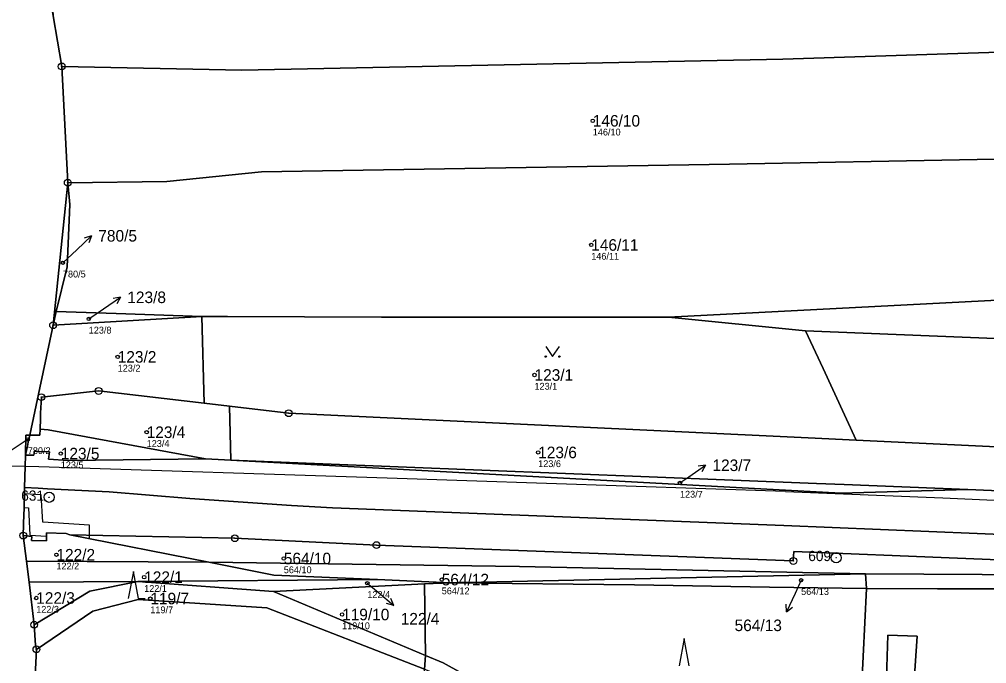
# Model space of a CAD drawing. Extents: x -732749 to -730903, y -1025757 to -1023435.
# Drawn here: x -732610 to -732467.8, y -1024807.5 to -1024712.7 of the extents above; entities that cross this region are included whole.
import ezdxf

# ---------------------------------------------------------------- set-up
doc = ezdxf.new("R2010")
doc.units = 0
for name, color, linetype in [('Definiční body', 7, 'Continuous'), ('Hranice parcel', 7, 'Continuous'), ('Parcelní čísla', 7, 'Continuous'), ('Polygon budovy', 7, 'Continuous'), ('Polygon parcely', 7, 'Continuous'), ('Pop  PČ popisy', 7, 'Continuous'), ('Poz předměty', 7, 'Continuous'), ('Věcná břemena k části', 7, 'Continuous'), ('Značky bodu BP', 7, 'Continuous'), ('Značky kultur', 7, 'Continuous')]:
    doc.layers.add(name, color=color, linetype=linetype)

msp = doc.modelspace()

# ---------------------------------------------------------------- linework, layer by layer
at = {"layer": 'Definiční body'}
for centre in [(-732525.66, -1024727.65), (-732525.89, -1024745.91), (-732603.56, -1024748.53), (-732599.77, -1024756.78), (-732595.51, -1024762.37), (-732534.23, -1024765.03), (-732591.25, -1024773.45), (-732608.73, -1024774.5), (-732603.88, -1024776.59), (-732533.69, -1024776.42), (-732512.84, -1024780.91), (-732604.52, -1024791.47), (-732571.09, -1024792.02), (-732591.62, -1024794.77), (-732547.87, -1024795.12), (-732495.03, -1024795.22), (-732558.81, -1024795.66), (-732607.49, -1024797.83), (-732590.71, -1024797.91), (-732562.52, -1024800.26)]:
    msp.add_circle(centre, 0.25, dxfattribs=at)
at = {"layer": 'Hranice parcel'}
for p, q in [((-732603.74, -1024719.65), (-732604.99, -1024712.19)), ((-732602.85, -1024736.75), (-732603.74, -1024719.65)), ((-732602.85, -1024736.75), (-732605.01, -1024757.71)), ((-732514.51, -1024756.52), (-732430.15, -1024752.17)), ((-732605.01, -1024757.71), (-732604.58, -1024755.68)), ((-732583.12, -1024756.45), (-732605.01, -1024757.71)), ((-732583.12, -1024756.45), (-732582.8, -1024769.2)), ((-732494.37, -1024758.56), (-732514.51, -1024756.52)), ((-732582.8, -1024769.2), (-732579.08, -1024769.64)), ((-732578.9, -1024777.57), (-732579.08, -1024769.64)), ((-732582.6, -1024777.37), (-732578.9, -1024777.57)), ((-732608.93, -1024792.4), (-732609.39, -1024788.65)), ((-732602.56, -1024788.52), (-732582.1, -1024792.58)), ((-732582.1, -1024792.58), (-732608.93, -1024792.4)), ((-732608.93, -1024792.4), (-732608.55, -1024795.52)), ((-732592.56, -1024795.4), (-732557.32, -1024795.12)), ((-732546.51, -1024795.58), (-732557.32, -1024795.12)), ((-732546.51, -1024795.58), (-732485.56, -1024794.26)), ((-732485.43, -1024796.42), (-732485.56, -1024794.26)), ((-732485.56, -1024794.26), (-732442.64, -1024794.52)), ((-732608.55, -1024795.52), (-732592.56, -1024795.4)), ((-732607.79, -1024801.77), (-732608.55, -1024795.52)), ((-732592.56, -1024795.4), (-732599.62, -1024796.8)), ((-732572.58, -1024796.88), (-732592.56, -1024795.4)), ((-732550.41, -1024795.77), (-732572.58, -1024796.88)), ((-732546.51, -1024795.58), (-732550.41, -1024795.77)), ((-732550.41, -1024795.77), (-732550.27, -1024806.28)), ((-732599.62, -1024796.8), (-732607.79, -1024801.77)), ((-732550.27, -1024806.28), (-732572.58, -1024796.88)), ((-732607.79, -1024801.77), (-732607.6, -1024804.78)), ((-732607.6, -1024804.78), (-732607.46, -1024805.38)), ((-732550.4, -1024808.31), (-732550.27, -1024806.28))]:
    msp.add_line(p, q, dxfattribs=at)
for points in [[(-732603.74, -1024719.65), (-732577.26, -1024720.21), (-732497.7, -1024718.61), (-732435.68, -1024716.6)], [(-732602.85, -1024736.75), (-732588.3, -1024736.57), (-732574.35, -1024735.17), (-732505.57, -1024734.04), (-732432.75, -1024732.67)], [(-732604.58, -1024755.68), (-732602.94, -1024749.11), (-732602.54, -1024739.97), (-732602.85, -1024736.75)], [(-732583.12, -1024756.45), (-732595.74, -1024756), (-732604.58, -1024755.68)], [(-732514.51, -1024756.52), (-732556.73, -1024756.51), (-732579.37, -1024756.45), (-732583.12, -1024756.45)], [(-732605.01, -1024757.71), (-732606.97, -1024766.94), (-732608.44, -1024773.87)], [(-732486.92, -1024774.63), (-732491.8, -1024764.09), (-732494.37, -1024758.56)], [(-732429.16, -1024761.7), (-732451.94, -1024760.24), (-732494.37, -1024758.56)], [(-732606.93, -1024773), (-732606.87, -1024771.48), (-732606.87, -1024770.65), (-732606.73, -1024768.29), (-732598.31, -1024767.38), (-732582.8, -1024769.2)], [(-732579.08, -1024769.64), (-732570.37, -1024770.66), (-732494.01, -1024774.29), (-732486.92, -1024774.63)], [(-732608.44, -1024773.87), (-732609.01, -1024773.86), (-732609.06, -1024776.81)], [(-732608.44, -1024773.87), (-732608.66, -1024774.93), (-732608.78, -1024775.48), (-732608.92, -1024776.13), (-732609.06, -1024776.81)], [(-732608.44, -1024773.87), (-732606.95, -1024773.88), (-732606.93, -1024773)], [(-732606.93, -1024773), (-732605.75, -1024773.12), (-732582.6, -1024777.37)], [(-732486.92, -1024774.63), (-732460.13, -1024775.9), (-732426.87, -1024778.43)], [(-732609.06, -1024776.81), (-732609.11, -1024778.5), (-732609.19, -1024781.6)], [(-732609.06, -1024776.81), (-732607.83, -1024776.81), (-732607.73, -1024776.23), (-732607.04, -1024776.26), (-732605.52, -1024776.32), (-732605.67, -1024777.42), (-732602.77, -1024777.63), (-732582.6, -1024777.37)], [(-732578.9, -1024777.57), (-732492.78, -1024780.98), (-732488.72, -1024781.14), (-732470.51, -1024781.88)], [(-732578.9, -1024777.57), (-732489.2, -1024782.39), (-732470.51, -1024781.88)], [(-732609.19, -1024781.6), (-732609.21, -1024782.24), (-732609.22, -1024782.52), (-732609.27, -1024784.52), (-732609.28, -1024784.79), (-732609.3, -1024785.43), (-732609.39, -1024788.65)], [(-732369.58, -1024795.34), (-732369.92, -1024794.44), (-732372.64, -1024792.79), (-732375.72, -1024792.25), (-732378.8, -1024792.04), (-732447.85, -1024789.23), (-732497.58, -1024787.17), (-732563.92, -1024784.56), (-732569.94, -1024784.24), (-732584.9, -1024783.22), (-732596.78, -1024782.21), (-732605.81, -1024781.79), (-732607.18, -1024781.66), (-732609.19, -1024781.6)], [(-732470.51, -1024781.88), (-732455.49, -1024782.49), (-732426.01, -1024783.68)], [(-732609.39, -1024788.65), (-732608.14, -1024788.8), (-732608.17, -1024789.39), (-732605.97, -1024789.44), (-732605.97, -1024788.27), (-732603.07, -1024788.35), (-732602.56, -1024788.52)], [(-732602.56, -1024788.52), (-732578.29, -1024789.04), (-732557.47, -1024790.05), (-732496.18, -1024792.38), (-732496.12, -1024790.97), (-732448, -1024792.93), (-732420.02, -1024794.07)], [(-732582.1, -1024792.58), (-732536.43, -1024793.21), (-732485.56, -1024794.26)], [(-732557.32, -1024795.12), (-732572.56, -1024794.47), (-732582.1, -1024792.58)], [(-732485.43, -1024796.42), (-732499.66, -1024796.22), (-732519.54, -1024795.9), (-732546.51, -1024795.58)], [(-732486.86, -1024825.68), (-732486.41, -1024816.41), (-732485.43, -1024796.42)], [(-732442.57, -1024796.49), (-732474.99, -1024796.48), (-732485.43, -1024796.42)], [(-732550.4, -1024808.31), (-732573.59, -1024799.29), (-732592.51, -1024798.07), (-732599.17, -1024799.75), (-732607.46, -1024805.38)], [(-732478.6, -1024812.92), (-732477.97, -1024803.45), (-732482.27, -1024803.31), (-732482.56, -1024812.7), (-732483.01, -1024812.67), (-732482.98, -1024816.43), (-732486.41, -1024816.41), (-732486.51, -1024822.83), (-732480.44, -1024822.93), (-732470.38, -1024823.14), (-732470.24, -1024816.4), (-732470.26, -1024814.3), (-732472.8, -1024814.19), (-732478.6, -1024814.1), (-732478.6, -1024812.92)], [(-732607.46, -1024805.38), (-732607.76, -1024811.21), (-732610.88, -1024850.88)], [(-732550.27, -1024806.28), (-732547.68, -1024807.37), (-732535.68, -1024813.99), (-732518.46, -1024823.83), (-732512.12, -1024826.36), (-732506.19, -1024827.78), (-732486.98, -1024830.41)]]:
    msp.add_lwpolyline(points, dxfattribs=at)
at = {"layer": 'Polygon budovy'}
msp.add_lwpolyline([(-732482.57, -1024812.99), (-732481.51, -1024812.81), (-732481.6, -1024816.44), (-732480.33, -1024816.52), (-732480.44, -1024822.93), (-732470.38, -1024823.14), (-732470.24, -1024816.4), (-732472.85, -1024816.34), (-732472.8, -1024814.19), (-732478.6, -1024814.1), (-732478.6, -1024812.92), (-732477.97, -1024803.45), (-732482.27, -1024803.31), (-732482.56, -1024812.7)], close=True, dxfattribs=at)
at = {"layer": 'Polygon parcely'}
for points in [[(-732607.76, -1024811.21), (-732607.46, -1024805.38), (-732607.6, -1024804.78), (-732607.79, -1024801.77), (-732608.55, -1024795.52), (-732608.93, -1024792.4), (-732609.39, -1024788.65), (-732609.3, -1024785.43), (-732609.28, -1024784.79), (-732609.27, -1024784.52), (-732609.22, -1024782.52), (-732609.21, -1024782.24), (-732609.19, -1024781.6), (-732609.11, -1024778.5), (-732609.06, -1024776.81), (-732609.01, -1024773.86), (-732608.44, -1024773.87), (-732606.97, -1024766.94), (-732605.01, -1024757.71), (-732602.85, -1024736.75), (-732603.74, -1024719.65), (-732604.99, -1024712.19), (-732607.31, -1024698.36), (-732611.24, -1024594.48)], [(-732455.49, -1024782.49), (-732470.51, -1024781.88), (-732489.2, -1024782.39), (-732578.9, -1024777.57), (-732582.6, -1024777.37), (-732602.77, -1024777.63), (-732605.67, -1024777.42), (-732605.52, -1024776.32), (-732607.04, -1024776.26), (-732607.73, -1024776.23), (-732607.83, -1024776.81), (-732609.06, -1024776.81), (-732609.11, -1024778.5), (-732609.19, -1024781.6), (-732607.18, -1024781.66), (-732605.81, -1024781.79), (-732596.78, -1024782.21), (-732584.9, -1024783.22), (-732569.94, -1024784.24), (-732563.92, -1024784.56), (-732497.58, -1024787.17), (-732447.85, -1024789.23)], [(-732447.85, -1024789.23), (-732497.58, -1024787.17), (-732563.92, -1024784.56), (-732569.94, -1024784.24), (-732584.9, -1024783.22), (-732596.78, -1024782.21), (-732605.81, -1024781.79), (-732607.18, -1024781.66), (-732609.19, -1024781.6), (-732609.21, -1024782.24), (-732609.22, -1024782.52), (-732609.27, -1024784.52), (-732609.28, -1024784.79), (-732609.3, -1024785.43), (-732609.39, -1024788.65), (-732608.14, -1024788.8), (-732608.17, -1024789.39), (-732605.97, -1024789.44), (-732605.97, -1024788.27), (-732603.07, -1024788.35), (-732602.56, -1024788.52), (-732578.29, -1024789.04), (-732557.47, -1024790.05), (-732496.18, -1024792.38), (-732496.12, -1024790.97), (-732448, -1024792.93)]]:
    msp.add_lwpolyline(points, dxfattribs=at)
for points in [[(-732577.26, -1024720.21), (-732497.7, -1024718.61), (-732435.68, -1024716.6), (-732438.93, -1024698.81), (-732441.15, -1024698.99), (-732470.31, -1024699.59), (-732479, -1024699.78), (-732497.59, -1024700.32), (-732497.8, -1024697.68), (-732523.82, -1024698.02), (-732605.8, -1024698.35), (-732605.62, -1024703.18), (-732604.99, -1024712.19), (-732603.74, -1024719.65)], [(-732432.75, -1024732.67), (-732435.68, -1024716.6), (-732497.7, -1024718.61), (-732577.26, -1024720.21), (-732603.74, -1024719.65), (-732602.85, -1024736.75), (-732588.3, -1024736.57), (-732574.35, -1024735.17), (-732505.57, -1024734.04)], [(-732514.51, -1024756.52), (-732430.15, -1024752.17), (-732431.44, -1024739.85), (-732432.75, -1024732.67), (-732505.57, -1024734.04), (-732574.35, -1024735.17), (-732588.3, -1024736.57), (-732602.85, -1024736.75), (-732602.54, -1024739.97), (-732602.94, -1024749.11), (-732604.58, -1024755.68), (-732595.74, -1024756), (-732583.12, -1024756.45), (-732579.37, -1024756.45), (-732556.73, -1024756.51)], [(-732605.01, -1024757.71), (-732604.58, -1024755.68), (-732602.94, -1024749.11), (-732602.54, -1024739.97), (-732602.85, -1024736.75)], [(-732514.51, -1024756.52), (-732494.37, -1024758.56), (-732451.94, -1024760.24), (-732429.16, -1024761.7), (-732430.15, -1024752.17)], [(-732606.97, -1024766.94), (-732608.44, -1024773.87), (-732606.95, -1024773.88), (-732606.93, -1024773), (-732606.87, -1024771.48), (-732606.87, -1024770.65), (-732606.73, -1024768.29), (-732598.31, -1024767.38), (-732582.8, -1024769.2), (-732583.12, -1024756.45), (-732605.01, -1024757.71)], [(-732595.74, -1024756), (-732604.58, -1024755.68), (-732605.01, -1024757.71), (-732583.12, -1024756.45)], [(-732486.92, -1024774.63), (-732491.8, -1024764.09), (-732494.37, -1024758.56), (-732514.51, -1024756.52), (-732556.73, -1024756.51), (-732579.37, -1024756.45), (-732583.12, -1024756.45), (-732582.8, -1024769.2), (-732579.08, -1024769.64), (-732570.37, -1024770.66), (-732494.01, -1024774.29)], [(-732429.16, -1024761.7), (-732451.94, -1024760.24), (-732494.37, -1024758.56), (-732491.8, -1024764.09), (-732486.92, -1024774.63), (-732460.13, -1024775.9), (-732426.87, -1024778.43), (-732427.58, -1024773.67), (-732428.01, -1024770.76)], [(-732605.75, -1024773.12), (-732582.6, -1024777.37), (-732578.9, -1024777.57), (-732579.08, -1024769.64), (-732582.8, -1024769.2), (-732598.31, -1024767.38), (-732606.73, -1024768.29), (-732606.87, -1024770.65), (-732606.87, -1024771.48), (-732606.93, -1024773)], [(-732470.51, -1024781.88), (-732455.49, -1024782.49), (-732426.01, -1024783.68), (-732426.87, -1024778.43), (-732460.13, -1024775.9), (-732486.92, -1024774.63), (-732494.01, -1024774.29), (-732570.37, -1024770.66), (-732579.08, -1024769.64), (-732578.9, -1024777.57), (-732492.78, -1024780.98), (-732488.72, -1024781.14)], [(-732605.52, -1024776.32), (-732605.67, -1024777.42), (-732602.77, -1024777.63), (-732582.6, -1024777.37), (-732605.75, -1024773.12), (-732606.93, -1024773), (-732606.95, -1024773.88), (-732608.44, -1024773.87), (-732608.66, -1024774.93), (-732608.78, -1024775.48), (-732608.92, -1024776.13), (-732609.06, -1024776.81), (-732607.83, -1024776.81), (-732607.73, -1024776.23), (-732607.04, -1024776.26)], [(-732608.44, -1024773.87), (-732609.01, -1024773.86), (-732609.06, -1024776.81), (-732608.92, -1024776.13), (-732608.78, -1024775.48), (-732608.66, -1024774.93)], [(-732489.2, -1024782.39), (-732470.51, -1024781.88), (-732488.72, -1024781.14), (-732492.78, -1024780.98), (-732578.9, -1024777.57)], [(-732602.56, -1024788.52), (-732603.07, -1024788.35), (-732605.97, -1024788.27), (-732605.97, -1024789.44), (-732608.17, -1024789.39), (-732608.14, -1024788.8), (-732609.39, -1024788.65), (-732608.93, -1024792.4), (-732582.1, -1024792.58)], [(-732485.56, -1024794.26), (-732442.64, -1024794.52), (-732420.02, -1024794.07), (-732448, -1024792.93), (-732496.12, -1024790.97), (-732496.18, -1024792.38), (-732557.47, -1024790.05), (-732578.29, -1024789.04), (-732602.56, -1024788.52), (-732582.1, -1024792.58), (-732536.43, -1024793.21)], [(-732608.55, -1024795.52), (-732592.56, -1024795.4), (-732557.32, -1024795.12), (-732572.56, -1024794.47), (-732582.1, -1024792.58), (-732608.93, -1024792.4)], [(-732546.51, -1024795.58), (-732485.56, -1024794.26), (-732536.43, -1024793.21), (-732582.1, -1024792.58), (-732572.56, -1024794.47), (-732557.32, -1024795.12)], [(-732557.32, -1024795.12), (-732592.56, -1024795.4), (-732572.58, -1024796.88), (-732550.41, -1024795.77), (-732546.51, -1024795.58)], [(-732485.56, -1024794.26), (-732546.51, -1024795.58), (-732519.54, -1024795.9), (-732499.66, -1024796.22), (-732485.43, -1024796.42)], [(-732442.64, -1024794.52), (-732485.56, -1024794.26), (-732485.43, -1024796.42), (-732474.99, -1024796.48), (-732442.57, -1024796.49)], [(-732599.62, -1024796.8), (-732592.56, -1024795.4), (-732608.55, -1024795.52), (-732607.79, -1024801.77)], [(-732599.62, -1024796.8), (-732607.79, -1024801.77), (-732607.6, -1024804.78), (-732607.46, -1024805.38), (-732599.17, -1024799.75), (-732592.51, -1024798.07), (-732573.59, -1024799.29), (-732550.4, -1024808.31), (-732550.27, -1024806.28), (-732572.58, -1024796.88), (-732592.56, -1024795.4)], [(-732550.41, -1024795.77), (-732572.58, -1024796.88), (-732550.27, -1024806.28)], [(-732485.43, -1024796.42), (-732499.66, -1024796.22), (-732519.54, -1024795.9), (-732546.51, -1024795.58), (-732550.41, -1024795.77), (-732550.27, -1024806.28), (-732547.68, -1024807.37), (-732535.68, -1024813.99), (-732518.46, -1024823.83), (-732512.12, -1024826.36), (-732506.19, -1024827.78), (-732486.98, -1024830.41), (-732486.86, -1024825.68), (-732486.41, -1024816.41)], [(-732443.16, -1024826.78), (-732442.57, -1024796.49), (-732474.99, -1024796.48), (-732485.43, -1024796.42), (-732486.41, -1024816.41), (-732486.86, -1024825.68), (-732466.9, -1024826.09)], [(-732607.46, -1024805.38), (-732607.76, -1024811.21), (-732610.88, -1024850.88), (-732603.34, -1024850.06), (-732586.1, -1024848.18), (-732568.22, -1024846.46), (-732552.65, -1024844.64), (-732550.4, -1024808.31), (-732573.59, -1024799.29), (-732592.51, -1024798.07), (-732599.17, -1024799.75)], [(-732478.6, -1024812.92), (-732477.97, -1024803.45), (-732482.27, -1024803.31), (-732482.56, -1024812.7), (-732483.01, -1024812.67), (-732482.98, -1024816.43), (-732486.41, -1024816.41), (-732486.51, -1024822.83), (-732480.44, -1024822.93), (-732470.38, -1024823.14), (-732470.24, -1024816.4), (-732470.26, -1024814.3), (-732472.8, -1024814.19), (-732478.6, -1024814.1)], [(-732478.6, -1024812.92), (-732478.6, -1024814.1), (-732472.8, -1024814.19), (-732470.26, -1024814.3), (-732470.24, -1024816.4), (-732470.38, -1024823.14), (-732480.44, -1024822.93), (-732486.51, -1024822.83), (-732486.41, -1024816.41), (-732482.98, -1024816.43), (-732483.01, -1024812.67), (-732482.56, -1024812.7), (-732482.27, -1024803.31), (-732477.97, -1024803.45)], [(-732486.98, -1024830.41), (-732506.19, -1024827.78), (-732512.12, -1024826.36), (-732518.46, -1024823.83), (-732535.68, -1024813.99), (-732547.68, -1024807.37), (-732550.27, -1024806.28), (-732550.4, -1024808.31), (-732548.41, -1024809.09), (-732536.73, -1024815.66), (-732519.36, -1024825.65), (-732512.8, -1024828.46), (-732506.56, -1024829.72), (-732487.16, -1024833.5)]]:
    msp.add_lwpolyline(points, close=True, dxfattribs=at)
at = {"layer": 'Pop  PČ popisy'}
for p, q in [((-732601.54, -1024746.62), (-732599.34, -1024744.57)), ((-732599.34, -1024744.57), (-732600.42, -1024744.89)), ((-732599.34, -1024744.57), (-732599.74, -1024745.62)), ((-732603.56, -1024748.53), (-732601.54, -1024746.62)), ((-732597.58, -1024755.29), (-732595.09, -1024753.61)), ((-732595.09, -1024753.61), (-732596.2, -1024753.76)), ((-732595.09, -1024753.61), (-732595.64, -1024754.59)), ((-732599.77, -1024756.78), (-732597.58, -1024755.29)), ((-732609.11, -1024774.76), (-732611.6, -1024776.44)), ((-732608.73, -1024774.5), (-732609.11, -1024774.76)), ((-732511.54, -1024780.01), (-732509.08, -1024778.29)), ((-732509.08, -1024778.29), (-732510.19, -1024778.45)), ((-732509.08, -1024778.29), (-732509.61, -1024779.27)), ((-732512.84, -1024780.91), (-732511.54, -1024780.01)), ((-732495.03, -1024795.22), (-732495.93, -1024797.15)), ((-732558.81, -1024795.66), (-732557.21, -1024796.99)), ((-732557.21, -1024796.99), (-732554.91, -1024798.92)), ((-732554.91, -1024798.92), (-732555.36, -1024797.89)), ((-732495.93, -1024797.15), (-732497.2, -1024799.87)), ((-732554.91, -1024798.92), (-732556, -1024798.66)), ((-732497.2, -1024799.87), (-732497.23, -1024798.75)), ((-732497.2, -1024799.87), (-732496.32, -1024799.17))]:
    msp.add_line(p, q, dxfattribs=at)
at = {"layer": 'Poz předměty'}
for p, q in [((-732609.11, -1024778.5), (-732617.72, -1024778.24)), ((-732607.11, -1024778.56), (-732609.11, -1024778.5)), ((-732555.89, -1024780.19), (-732607.11, -1024778.56)), ((-732497.35, -1024782.19), (-732555.89, -1024780.19)), ((-732497.35, -1024782.19), (-732474.18, -1024783.11)), ((-732474.18, -1024783.11), (-732447.65, -1024784.31))]:
    msp.add_line(p, q, dxfattribs=at)
at = {"layer": 'Věcná břemena k části'}
msp.add_lwpolyline([(-732609.22, -1024782.52), (-732609.27, -1024784.52), (-732608.64, -1024784.59), (-732608.42, -1024788.58), (-732605.97, -1024788.73), (-732605.97, -1024788.27), (-732603.07, -1024788.35), (-732602.56, -1024788.52), (-732599.64, -1024789.1), (-732599.65, -1024787.1), (-732606.52, -1024786.69), (-732606.74, -1024782.65)], close=True, dxfattribs=at)
at = {"layer": 'Značky bodu BP'}
for centre, radius in [((-732603.74, -1024719.65), 0.5), ((-732603.74, -1024719.65), 0.0303), ((-732602.85, -1024736.75), 0.5), ((-732602.85, -1024736.75), 0.0303), ((-732605.01, -1024757.71), 0.5), ((-732605.01, -1024757.71), 0.0303), ((-732598.31, -1024767.38), 0.5), ((-732606.73, -1024768.29), 0.5), ((-732606.73, -1024768.29), 0.0303), ((-732598.31, -1024767.38), 0.0303), ((-732570.37, -1024770.66), 0.5), ((-732570.37, -1024770.66), 0.0303), ((-732605.59, -1024783.02), 0.75), ((-732605.59, -1024783.02), 0.03), ((-732609.39, -1024788.65), 0.5), ((-732609.39, -1024788.65), 0.0303), ((-732578.29, -1024789.04), 0.5), ((-732578.29, -1024789.04), 0.0303), ((-732557.47, -1024790.05), 0.5), ((-732557.47, -1024790.05), 0.0303), ((-732496.18, -1024792.38), 0.5), ((-732496.18, -1024792.38), 0.0303), ((-732489.88, -1024791.9), 0.75), ((-732489.88, -1024791.9), 0.03), ((-732607.79, -1024801.77), 0.5), ((-732607.79, -1024801.77), 0.0303), ((-732607.46, -1024805.38), 0.5), ((-732607.46, -1024805.38), 0.0303)]:
    msp.add_circle(centre, radius, dxfattribs=at)
at = {"layer": 'Značky kultur'}
for p, q in [((-732593.21, -1024793.91), (-732593.96, -1024797.91)), ((-732592.46, -1024797.91), (-732593.21, -1024793.91)), ((-732592.46, -1024797.91), (-732591.46, -1024797.91)), ((-732512.23, -1024803.8), (-732512.98, -1024807.8)), ((-732511.48, -1024807.8), (-732512.23, -1024803.8))]:
    msp.add_line(p, q, dxfattribs=at)
msp.add_lwpolyline([(-732532.57, -1024760.83), (-732531.57, -1024762.33), (-732530.57, -1024760.83)], dxfattribs=at)
for centre in [(-732532.57, -1024762.33), (-732530.57, -1024762.33)]:
    msp.add_circle(centre, 0.1, dxfattribs=at)

# ---------------------------------------------------------------- texts
at = {"layer": 'Definiční body'}
for s, p in [('146/10', (-732525.66, -1024729.81)), ('146/11', (-732525.89, -1024748.07)), ('780/5', (-732603.56, -1024750.69)), ('123/8', (-732599.77, -1024758.94)), ('123/2', (-732595.51, -1024764.53)), ('123/1', (-732534.23, -1024767.19)), ('123/4', (-732591.25, -1024775.61)), ('780/2', (-732608.73, -1024776.66)), ('123/5', (-732603.88, -1024778.75)), ('123/6', (-732533.69, -1024778.58)), ('123/7', (-732512.84, -1024783.07)), ('122/2', (-732604.52, -1024793.63)), ('564/10', (-732571.09, -1024794.18)), ('122/1', (-732591.62, -1024796.93)), ('122/4', (-732558.81, -1024797.82)), ('564/12', (-732547.87, -1024797.28)), ('564/13', (-732495.03, -1024797.38)), ('122/3', (-732607.49, -1024799.99)), ('119/7', (-732590.71, -1024800.07)), ('119/10', (-732562.52, -1024802.42))]:
    msp.add_text(s, height=1, dxfattribs=at).set_placement(p)
at = {"layer": 'Parcelní čísla'}
for s, p in [('146/10', (-732525.66, -1024728.5)), ('780/5', (-732598.36, -1024745.41)), ('146/11', (-732525.89, -1024746.76)), ('123/8', (-732594.1, -1024754.46)), ('123/2', (-732595.51, -1024763.22)), ('123/1', (-732534.23, -1024765.88)), ('123/4', (-732591.25, -1024774.3)), ('123/5', (-732603.88, -1024777.44)), ('123/6', (-732533.69, -1024777.27)), ('123/7', (-732508.07, -1024779.16)), ('122/2', (-732604.52, -1024792.32)), ('564/10', (-732571.09, -1024792.87)), ('122/1', (-732591.62, -1024795.62)), ('564/12', (-732547.87, -1024795.97)), ('122/3', (-732607.49, -1024798.68)), ('119/7', (-732590.71, -1024798.76)), ('119/10', (-732562.52, -1024801.11)), ('122/4', (-732553.9, -1024801.73)), ('564/13', (-732504.81, -1024802.7))]:
    msp.add_text(s, height=1.7, dxfattribs=at).set_placement(p)
at = {"layer": 'Značky bodu BP'}
for s, p in [('631', (-732609.69, -1024783.52)), ('609', (-732493.98, -1024792.4))]:
    msp.add_text(s, height=1.5, dxfattribs=at).set_placement(p)

doc.saveas('drawing.dxf')
